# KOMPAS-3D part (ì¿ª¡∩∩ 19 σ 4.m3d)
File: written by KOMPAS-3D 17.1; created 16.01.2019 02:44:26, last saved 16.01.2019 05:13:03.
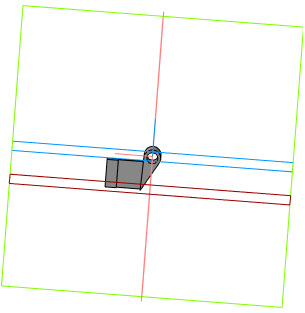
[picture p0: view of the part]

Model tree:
1. Эскиз:1
2. Элемент выдавливания:1
     Расстояние 1 = 9.5; Расстояние 2 = 9.5
3. Смещенная плоскость:1
     Расстояние = 5.9
4. Эскиз:2
5. Элемент выдавливания:2
     Расстояние 1 = 4.9
6. Эскиз:3
7. Элемент выдавливания:3
     Расстояние 1 = 3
